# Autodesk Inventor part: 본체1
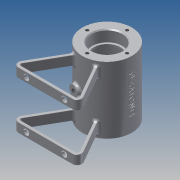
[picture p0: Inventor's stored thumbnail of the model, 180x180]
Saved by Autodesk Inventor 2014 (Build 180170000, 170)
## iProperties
Created: 2016-03
Part Number: 본체1
Material: 알루미늄 6061
Document SubType Name: Modeling
Designer: 406-003
Density: 2.71 g/cm^3
Appearance: 알루미늄 - 평지
Mass: 210.237 g
Surface Area: 325.992 cm^2
Volume: 77.5781 cm^3
Author: 406-003
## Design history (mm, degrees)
sketch "스케치1"
  geometry: C1 r 26 at (0, 0); 1 further point
  constraints: 1 centre point, 1 coincident
  dimensions: "d0" = 52 diameter of C1
extrude "돌출1" new body sketch "스케치1" distance "d1" = 70; taper "d2" = 0 deg
sketch "스케치2"
  geometry: C1 r 26 at (0, 0) reference; 1 further point
  constraints: 1 coincident
hole "구멍1" sketch "스케치2" at (0, 0) diameter "d4" = 28; stored, may be unused: countersink angle "d8" = 90 deg, drill point angle "d10" = 0 deg; dims "d5" = 6, "d6" = 32, "d7" = 12, "d9" = 14
fillet "모깎기1" dims "d11" = 0.3
node "작업 평면1"
sketch "스케치4"
  geometry: L1 (14, -14)-(-14, -14) reference; L2 (14, -56)-(-14, -56) reference; L3 (0, -14)-(0, -56); L4 (21, -14)-(21, -56); L5 (0, -14)-(21, -14); L6 (0, -56)-(21, -56); 1 further point
  constraints: 8 end point, 2 midpoint, 1 parallel, 1 perpendicular, 1 point on line
  dimensions: "d13" = 42 diameter of L4 L3
revolve "회전1" sketch "스케치4" stored, may be unused: angle "d14" = 90 deg
fillet "모깎기2" dims "d15" = 3
fillet "모깎기3" dims "d16" = 0.3
chamfer "모따기1" distance "d17" = 1; stored, may be unused: second distance "d18" = 2, angle "d19" = 45 deg
sketch "스케치5"
  geometry: L1 (0, 21)-(0, -21); C1 r 17 at (0, 0) reference; A1 r 21 centre (0, 0) between (0, 21) and (0, -21)
  constraints: 2 end point, 2 point on circle, 1 centre point, 1 coincident, 1 vertical
  dimensions: "d20" = 42 diameter of A1; "d21" = 0 distance from line of C1.centre L1
hole "구멍2" sketch "스케치5" at (0, 21) diameter "d22" = 3.242; stored, may be unused: countersink angle "d26" = 90 deg, drill point angle "d28" = 118 deg; dims "d23" = 8, "d24" = 32, "d25" = 12, "d27" = 10
node "작업 평면3"
  node "작업 평면2"
sketch "스케치6"
  geometry: L1 (0, 0)-(0, -35); C1 r 5 at (0, -35)
  constraints: 2 end point, 1 centre point, 1 coincident, 1 vertical
  dimensions: "d33" = 35 distance of L1.start L1.end; "d34" = 10 diameter of C1
extrude "돌출2" join sketch "스케치6" stored distance "d35" = 42; taper "d36" = 0 deg
fillet "모깎기4" dims "d37" = 2
sketch "스케치7"
  geometry: C1 r 5 at (0, 0) reference; 2 further points
  constraints: 1 coincident
hole "구멍3" sketch "스케치7" at (0, 0) diameter "d38" = 5.188; stored, may be unused: countersink angle "d42" = 90 deg, drill point angle "d44" = 118 deg; dims "d39" = 19, "d40" = 32, "d41" = 12, "d43" = 20
sketch "스케치8"
  geometry: L1 (0, 0)-(0, -26); L2 (0, 0)-(-7.506, -28.012); C1 r 1.621 at (21, 0) reference; C2 r 1.621 at (0, -21) reference; C3 r 1.621 at (-21, 0) reference; C4 r 1.621 at (0, 21) reference; C5 r 17 at (0, 0) reference; 1 further point
  constraints: 4 end point, 1 vertical, 1 vertical alignment, 1 other
  dimensions: "d46" = 15 deg angle of L2 L1; "d47" = 29 distance of L1.start L2.end
node "작업 평면5"
sketch "스케치9"
  geometry: L1 (0, 0)-(0, -35); C1 r 6 at (0, -35)
  constraints: 2 end point, 1 centre point, 1 coincident, 1 vertical
  dimensions: "d48" = 35 distance of L1.start L1.end; "d49" = 12 diameter of C1
extrude "돌출3" join sketch "스케치9" stored distance "d50" = 42; taper "d51" = 0 deg
sketch "스케치10"
  geometry: C1 r 6 at (0, 0) reference; 2 further points
  constraints: 1 coincident
hole "구멍4" sketch "스케치10" at (0, 0) diameter "d52" = 5.188; stored, may be unused: countersink angle "d56" = 90 deg, drill point angle "d58" = 118 deg; dims "d53" = 19, "d54" = 32, "d55" = 12, "d57" = 20
fillet "모깎기5" dims "d59" = 2
node "작업 평면6"
sketch "스케치11"
  geometry: L1 (0, 0)-(0, -65); L2 (0, -65)-(28.565, -65); L3 (0, -65)-(-28.565, -65); L4 (28.565, -62)-(0, -62); L5 (-28.565, -62)-(0, -62); L6 (-9.499, -22.57)-(-30.301, -59.008); L7 (-11.244, -20)-(-32.895, -57.5); L8 (9.491, -22.573)-(30.301, -59.008); L9 (11.244, -20)-(32.895, -57.5); C1 r 21 at (0, 0) reference; A1 r 5 centre (-28.565, -60) between (-32.895, -57.5) and (-28.565, -65); A2 r 5 centre (28.565, -60) between (28.565, -65) and (32.895, -57.5); A3 r 2 centre (28.565, -60) between (28.565, -62) and (30.301, -59.008); A4 r 2 centre (-28.565, -60) between (-30.301, -59.008) and (-28.565, -62); A5 r 22.944 centre (0, 0) between (-11.244, -20) and (11.244, -20); A6 r 3.457 centre (-28.565, -60) between (-31.699, -61.457) and (-31.384, -62); A7 r 24.487 centre (0, 0) between (-9.499, -22.57) and (9.491, -22.573)
  constraints: 18 end point, 14 point on circle, 7 centre point, 6 tangent, 2 point on line, 1 coincident, 1 collinear, 1 equal radius, 1 perpendicular, 1 vertical, 2 other
  dimensions: "d61" = 65 distance of L1.start L1.end; "d64" = 5 radius of A1; "d65" = 3 distance between parallel lines of L3 L5; "d66" = 3 distance between parallel lines of L2 L4; "d67" = 45 distance from line of L2 L9.start; "d68" = 45 distance from line of L3 L7.start; "d71" = 0.266242 deg angle of L8 L9; "d79" = 24.4874 radius of A7; "d80" = 22.94403 radius of A5; "d81" = 3.45663 radius of A6; "d104" = 30 deg angle of L1 L7; "d105" = 30 deg angle of L9 L1; "d106" = 59.7218 deg angle of L6 L9; "d107" = 30.73763 distance from line of L4.end L9; "d108" = 30.73763 distance from line of L5.end L9
extrude "돌출4" join sketch "스케치11" distance "d82" = 10; taper "d83" = 0 deg
sketch "스케치12"
  geometry: L1 (-32.895, -57.5)-(-12.772, -22.647) reference; L2 (12.772, -22.647)-(32.895, -57.5) reference; L3 (-9.491, -22.573)-(-30.301, -59.008) reference; L4 (9.499, -22.57)-(30.301, -59.008) reference; L5 (28.565, -62)-(0, -62) reference; L6 (-28.565, -62)-(0, -62) reference; A1 r 26 centre (0, 0) between (-12.772, -22.647) and (12.772, -22.647) reference; A2 r 24.487 centre (0, 0) between (-9.491, -22.573) and (9.499, -22.57) reference; A3 r 2 centre (28.565, -60) between (28.565, -62) and (30.301, -59.008) reference; A4 r 2 centre (-28.565, -60) between (-30.301, -59.008) and (-28.565, -62) reference; A5 r 26 centre (0, 0) between (-10.246, -23.896) and (10.254, -23.893); A6 r 26 centre (0, 0) between (12.772, -22.647) and (-12.772, -22.647)
  constraints: 4 point on circle, 2 centre point, 2 end point, 2 point on line, 1 coincident
  dimensions: "d84" = 26 radius of A5
extrude "돌출5" cut sketch "스케치12" distance "d85" = 10; taper "d86" = 0 deg
sketch "스케치13"
  geometry: L1 (0, 0)-(57.129, 0) reference; L2 (57.129, -10)-(0, -10) reference; L3 (28.565, 0)-(28.565, -10); L4 (8.565, 0)-(8.565, -10); L5 (48.565, 0)-(48.565, -10); C1 r 3 at (8.565, -5); C2 r 3 at (48.565, -5); 1 further point
  constraints: 6 end point, 4 midpoint, 2 centre point, 2 parallel
  dimensions: "d87" = 40 distance between parallel lines of L5 L4; "d88" = 20 distance between parallel lines of L3 L4; "d89" = 5 distance from line of L1 C1.centre; "d90" = 6 diameter of C1; "d91" = 6 diameter of C2; "d92" = 5 distance from line of C2.centre L1
extrude "돌출6" cut sketch "스케치13" distance "d93" = 10; taper "d94" = 0 deg
fillet "모깎기6" dims "d95" = 0.5
fillet "모깎기7" dims "d96" = 0.5
fillet "모깎기8" dims "d97" = 3
node "작업 평면8"
node "작업 평면9"
sketch "스케치16"
  geometry: L1 (0, 0)-(0, -35); 1 further point
  constraints: 2 end point, 1 coincident, 1 vertical, 1 other
  dimensions: "d101" = 35 distance of L1.start L1.end
feature "엠보싱2" sketch "스케치16" dims "d0" = 52, "d102" = 0.5, "d103" = 0
node "솔리드1"
mirror "대칭1"
pattern_circular "원형 패턴1" dims angle "d30" = 360 deg
mirror "대칭2"
mirror "대칭3"
mirror "대칭4"
other parameters: "d32" = 3, "d62" = 30 deg, "d63" = 30 deg, "d70" = 22.94403
